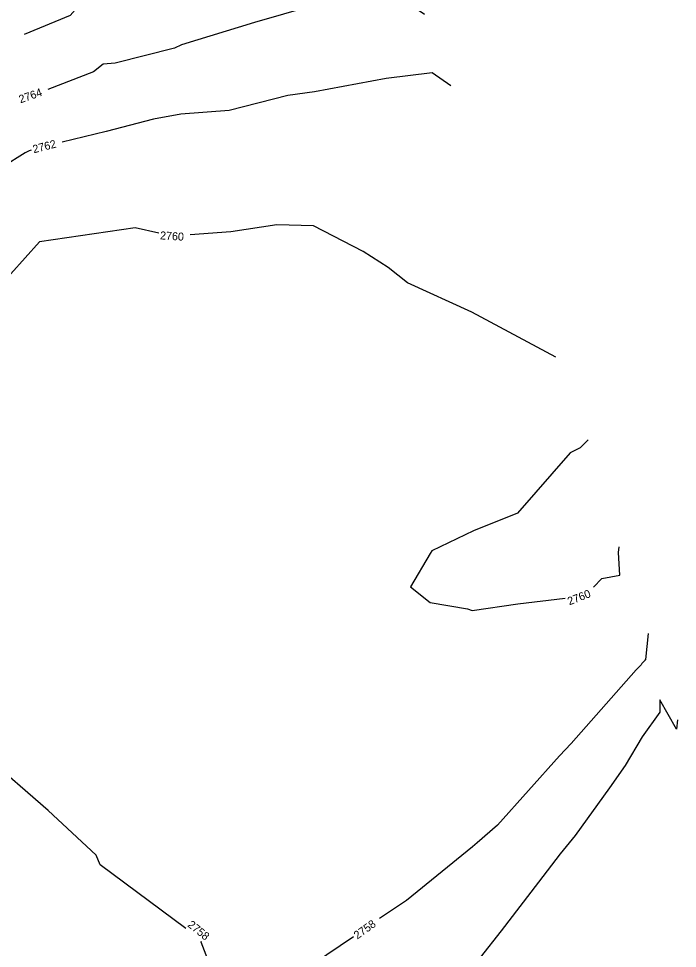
# Model space of a CAD drawing. Extents: x 1326424 to 1329294, y 1001359 to 1003823.
# Drawn here: x 1329054.3 to 1329219, y 1001900.5 to 1002132.9 of the extents above; entities that cross this region are included whole.
import ezdxf

# ---------------------------------------------------------------- set-up
doc = ezdxf.new("R2010")
doc.units = 0
doc.layers.add('Prop Rem of Exist Asph Pvmt', color=7, linetype='Continuous')
doc.layers.add('Scratch_Level_3', color=7, linetype='Continuous')

msp = doc.modelspace()

# ---------------------------------------------------------------- linework, layer by layer
at = {"layer": 'Prop Rem of Exist Asph Pvmt'}
for points in [[(1329089.3, 1002079.34), (1329083.39, 1002080.67), (1329059.51, 1002077.12), (1329052.3, 1002069.17), (1329051.39, 1002068.16), (1329049.82, 1002067.11), (1329038.06, 1002056.14), (1329035.55, 1002051.09), (1329034.71, 1002050), (1329034.22, 1002049.09), (1329019.15, 1002029.71), (1329016.64, 1002036.41)], [(1329188.55, 1002048.3), (1329167.57, 1002059.54), (1329151.47, 1002066.86), (1329146.67, 1002070.73), (1329140.44, 1002074.72), (1329127.97, 1002081.11), (1329118.8, 1002081.4), (1329107.36, 1002079.67), (1329097.19, 1002078.87)], [(1329196.68, 1002027.65), (1329194.67, 1002025.66), (1329192.13, 1002024.4), (1329179.01, 1002009.33), (1329167.95, 1002004.89), (1329157.53, 1001999.92), (1329157.13, 1001999.23), (1329152.27, 1001990.89), (1329157.12, 1001987.01), (1329166.52, 1001985.41), (1329167.69, 1001984.96), (1329179.1, 1001986.66), (1329190.93, 1001988.03)], [(1329197.96, 1001990.79), (1329200.04, 1001992.98), (1329204.56, 1001993.78), (1329204.27, 1001999.51), (1329204.41, 1002000.92)]]:
    msp.add_lwpolyline(points, dxfattribs=at)
at = {"layer": 'Scratch_Level_3'}
for points in [[(1329149.14, 1002151.82), (1329144.88, 1002154.79), (1329140.22, 1002156.2), (1329136.73, 1002155.47), (1329116.58, 1002147.51), (1329105.59, 1002146.11), (1329099.77, 1002143.91), (1329091.5, 1002140.65), (1329082.46, 1002136.43), (1329079.07, 1002135.57), (1329072.7, 1002135.02), (1329068.42, 1002135.14), (1329067.2, 1002133.76), (1329055.62, 1002128.98)], [(1329155.75, 1002133.97), (1329147.73, 1002139.54), (1329146.14, 1002140.02), (1329129.95, 1002136.67), (1329127.7, 1002136.12), (1329113.21, 1002131.99), (1329094.95, 1002126.35), (1329093.25, 1002125.56), (1329078.37, 1002121.8), (1329075.38, 1002121.54), (1329073, 1002119.64), (1329061.54, 1002115.24)], [(1329162.35, 1002116.12), (1329157.63, 1002119.4), (1329146.15, 1002117.99), (1329128.24, 1002114.67), (1329121.55, 1002113.73), (1329106.87, 1002109.94), (1329094.85, 1002109.05), (1329087.97, 1002107.79), (1329076.15, 1002104.72), (1329065.17, 1002102.07)], [(1329057.43, 1002100.07), (1329056.94, 1002099.88), (1329055.93, 1002099.4), (1329044.69, 1002092.36), (1329036.15, 1002085.66), (1329029.38, 1002073.72), (1329022.22, 1002082.81), (1329017, 1002085.06), (1329014.39, 1002081.39), (1329011.68, 1002078.49), (1329001.28, 1002065.62), (1328994.25, 1002061.23), (1328988, 1002053.47)], [(1329211.69, 1001979.27), (1329211.02, 1001972.71), (1329210.96, 1001972.82), (1329210.96, 1001972.62), (1329210.1, 1001971.7), (1329209.92, 1001971.44), (1329208.69, 1001970.18), (1329192.39, 1001951.71), (1329189.47, 1001948.64), (1329174.02, 1001931.32), (1329168.94, 1001926.89), (1329167.75, 1001925.92), (1329167.7, 1001925.89), (1329151.2, 1001912.5), (1329144.47, 1001908.03)], [(1329218.96, 1001957.62), (1329218.73, 1001955.36), (1329214.54, 1001962.68), (1329214.58, 1001959.61), (1329210.14, 1001953.43), (1329205.86, 1001946.25), (1329202, 1001940.69), (1329193.38, 1001928.7), (1329189.62, 1001924.14), (1329184.21, 1001917.08), (1329174.87, 1001904.87), (1329169.64, 1001898.23), (1329164.73, 1001893.32), (1329162.17, 1001891.51)], [(1329096.08, 1001905.51), (1329074.67, 1001921.43), (1329073.65, 1001923.81), (1329061.69, 1001934.95), (1329045.7, 1001948.84), (1329045.19, 1001948.85), (1329026.27, 1001944.05), (1329025.91, 1001944.13), (1329014.77, 1001937.82)], [(1329137.98, 1001903.38), (1329121.57, 1001892.33), (1329116.71, 1001888.64), (1329116.15, 1001888.47), (1329101.59, 1001870.1), (1329101.18, 1001869.26), (1329099.55, 1001867.32), (1329098.09, 1001863.58), (1329097.35, 1001868.56), (1329096.72, 1001871.54), (1329105.93, 1001886.52), (1329099.92, 1001902.1), (1329100.02, 1001902.32)]]:
    msp.add_lwpolyline(points, dxfattribs=at)

# ---------------------------------------------------------------- texts
at = {"layer": 'Prop Rem of Exist Asph Pvmt'}
for rotation, p in [(356.5759, (1329089.59, 1002077.77)), (21.4352, (1329191.95, 1001986.26))]:
    msp.add_text('2760', height=2, rotation=rotation, dxfattribs=at).set_placement(p)
at = {"layer": 'Scratch_Level_3'}
for s, rotation, p in [('2764', 19.3907, (1329054.74, 1002111.75)), ('2762', 14.4679, (1329058.07, 1002099.27)), ('2758', 320.9719, (1329096.34, 1001906.14)), ('2758', 35.6076, (1329138.95, 1001902.73))]:
    msp.add_text(s, height=2, rotation=rotation, dxfattribs=at).set_placement(p)

doc.saveas('drawing.dxf')
